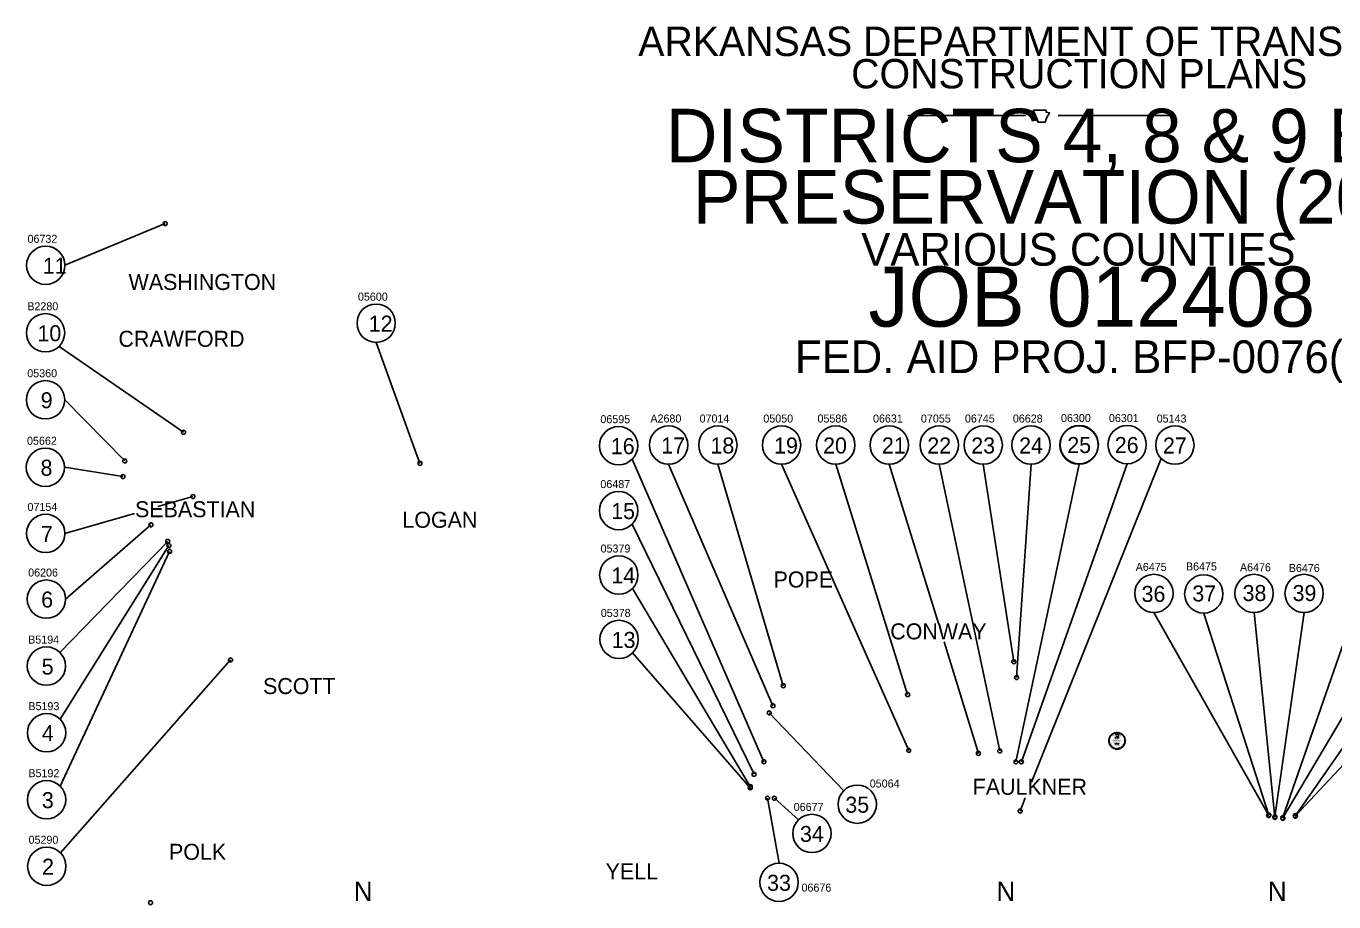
# Model space of a CAD drawing. Extents: x -13171 to 18763, y -8840 to 11152.
# Drawn here: x -13171 to 6418, y -1964 to 11152 of the extents above; entities that cross this region are included whole.
import ezdxf

# ---------------------------------------------------------------- set-up
doc = ezdxf.new("R2010")
doc.units = 0
for name, color, linetype in [('Level 1', 7, 'Continuous'), ('Level 2', 7, 'Continuous'), ('Level 46', 7, 'Continuous'), ('Level 48', 7, 'Continuous'), ('Level 50', 7, 'Continuous')]:
    doc.layers.add(name, color=color, linetype=linetype)

msp = doc.modelspace()

# ---------------------------------------------------------------- linework, layer by layer
at = {"layer": 'Level 1'}
for p, q in [((39, 9812), (1800, 9812)), ((2289, 9812), (4051, 9812))]:
    msp.add_line(p, q, dxfattribs=at)
msp.add_lwpolyline([(1915, 9901), (1952, 9803), (1952, 9743), (1982, 9736), (1982, 9714), (2094, 9714), (2116, 9773), (2161, 9856), (2108, 9862), (2108, 9893), (1923, 9893)], dxfattribs=at)
at = {"layer": 'Level 46'}
for p, q in [((3047, 438), (3046, 443)), ((3047, 458), (3047, 464)), ((3047, 448), (3047, 453)), ((3048, 428), (3047, 433)), ((3048, 468), (3049, 474)), ((3050, 418), (3049, 423)), ((3051, 478), (3052, 484)), ((3053, 408), (3051, 413)), ((3052, 450), (3053, 456)), ((3052, 441), (3052, 446)), ((3053, 460), (3054, 466)), ((3053, 431), (3053, 436)), ((3054, 488), (3055, 493)), ((3054, 470), (3056, 475)), ((3055, 421), (3054, 427)), ((3057, 398), (3055, 403)), ((3058, 412), (3056, 417)), ((3057, 498), (3059, 503)), ((3057, 479), (3058, 485)), ((3061, 403), (3059, 408)), ((3061, 389), (3059, 394)), ((3060, 489), (3062, 494)), ((3062, 507), (3064, 512)), ((3065, 394), (3063, 399)), ((3064, 498), (3066, 503)), ((3067, 516), (3070, 520)), ((3068, 506), (3071, 511)), ((3073, 524), (3076, 528)), ((3073, 515), (3077, 519)), ((3079, 523), (3083, 527)), ((3080, 532), (3083, 536)), ((3086, 530), (3090, 534)), ((3087, 539), (3091, 543)), ((3093, 537), (3097, 540)), ((3095, 546), (3099, 549)), ((3100, 543), (3105, 546)), ((3103, 552), (3108, 555)), ((3108, 548), (3113, 551)), ((3112, 557), (3117, 559)), ((3117, 553), (3122, 555)), ((3121, 561), (3126, 564)), ((3126, 557), (3131, 559)), ((3131, 565), (3136, 567)), ((3135, 560), (3140, 562)), ((3141, 568), (3146, 569)), ((3153, 499), (3142, 499)), ((3142, 499), (3151, 492)), ((3153, 404), (3142, 404)), ((3142, 404), (3151, 398)), ((3148, 503), (3144, 492)), ((3144, 492), (3153, 499)), ((3148, 408), (3144, 398)), ((3144, 398), (3153, 404)), ((3145, 563), (3150, 564)), ((3147, 497), (3148, 497)), ((3147, 402), (3148, 402)), ((3151, 492), (3148, 503)), ((3148, 498), (3148, 496)), ((3151, 398), (3148, 408)), ((3148, 403), (3148, 402)), ((3151, 570), (3156, 571)), ((3154, 565), (3160, 565)), ((3161, 571), (3167, 572)), ((3164, 566), (3169, 566)), ((3176, 499), (3165, 499)), ((3165, 499), (3174, 492)), ((3176, 404), (3165, 404)), ((3165, 404), (3174, 398)), ((3171, 503), (3167, 492)), ((3167, 492), (3176, 499)), ((3171, 408), (3167, 398)), ((3167, 398), (3176, 404)), ((3170, 497), (3172, 497)), ((3170, 402), (3172, 402)), ((3171, 571), (3177, 571)), ((3174, 492), (3171, 503)), ((3171, 498), (3171, 496)), ((3174, 398), (3171, 408)), ((3171, 403), (3171, 402)), ((3174, 566), (3179, 565)), ((3182, 571), (3187, 571)), ((3184, 565), (3189, 564)), ((3199, 499), (3188, 499)), ((3188, 499), (3197, 492)), ((3199, 404), (3188, 404)), ((3188, 404), (3197, 398)), ((3194, 503), (3190, 492)), ((3190, 492), (3199, 499)), ((3194, 408), (3190, 398)), ((3190, 398), (3199, 404)), ((3192, 570), (3197, 569)), ((3193, 564), (3198, 562)), ((3193, 497), (3195, 497)), ((3193, 402), (3195, 402)), ((3197, 492), (3194, 503)), ((3194, 498), (3194, 496)), ((3197, 398), (3194, 408)), ((3194, 403), (3194, 402)), ((3202, 568), (3207, 566)), ((3203, 561), (3208, 560)), ((3212, 565), (3217, 563)), ((3212, 558), (3217, 556)), ((3221, 561), (3226, 559)), ((3221, 555), (3226, 552)), ((3230, 556), (3235, 554)), ((3230, 550), (3234, 547)), ((3238, 545), (3242, 542)), ((3239, 551), (3244, 548)), ((3246, 539), (3250, 535)), ((3247, 545), (3252, 542)), ((3253, 532), (3257, 528)), ((3255, 538), (3259, 535)), ((3260, 525), (3263, 521)), ((3262, 531), (3266, 527)), ((3266, 518), (3269, 513)), ((3269, 523), (3272, 519)), ((3271, 510), (3274, 505)), ((3275, 515), (3278, 510)), ((3278, 397), (3275, 392)), ((3276, 501), (3278, 496)), ((3280, 506), (3283, 501)), ((3280, 492), (3282, 487)), ((3282, 406), (3280, 401)), ((3284, 397), (3282, 392)), ((3285, 415), (3283, 410)), ((3284, 483), (3285, 478)), ((3285, 497), (3287, 492)), ((3286, 474), (3287, 468)), ((3287, 425), (3286, 420)), ((3288, 407), (3286, 401)), ((3288, 487), (3290, 482)), ((3288, 464), (3288, 458)), ((3288, 435), (3288, 429)), ((3289, 454), (3289, 449)), ((3289, 444), (3289, 439)), ((3291, 416), (3290, 411)), ((3291, 477), (3293, 472)), ((3293, 426), (3292, 421)), ((3293, 467), (3294, 462)), ((3294, 457), (3295, 452)), ((3294, 437), (3294, 431)), ((3295, 447), (3295, 441)), ((3066, 380), (3063, 385)), ((3070, 385), (3067, 390)), ((3072, 372), (3069, 376)), ((3075, 377), (3072, 382)), ((3079, 364), (3075, 368)), ((3082, 369), (3078, 374)), ((3086, 357), (3082, 360)), ((3088, 362), (3085, 366)), ((3094, 350), (3090, 353)), ((3096, 356), (3092, 360)), ((3102, 344), (3098, 347)), ((3103, 350), (3099, 353)), ((3111, 339), (3106, 341)), ((3112, 345), (3107, 348)), ((3120, 334), (3115, 336)), ((3120, 340), (3116, 343)), ((3129, 336), (3124, 339)), ((3130, 330), (3125, 332)), ((3139, 333), (3134, 335)), ((3140, 327), (3134, 329)), ((3148, 331), (3143, 332)), ((3150, 325), (3144, 326)), ((3158, 330), (3152, 331)), ((3160, 324), (3154, 324)), ((3168, 329), (3162, 329)), ((3170, 323), (3165, 323)), ((3177, 329), (3172, 329)), ((3180, 324), (3175, 323)), ((3187, 330), (3182, 330)), ((3190, 325), (3185, 324)), ((3197, 332), (3191, 331)), ((3201, 327), (3195, 326)), ((3206, 334), (3201, 333)), ((3210, 330), (3205, 328)), ((3215, 338), (3210, 336)), ((3220, 334), (3215, 331)), ((3224, 342), (3219, 340)), ((3229, 338), (3224, 335)), ((3233, 347), (3228, 344)), ((3238, 343), (3234, 340)), ((3241, 352), (3236, 349)), ((3246, 349), (3242, 346)), ((3249, 358), (3244, 355)), ((3254, 356), (3250, 352)), ((3256, 365), (3252, 361)), ((3262, 363), (3258, 359)), ((3262, 372), (3259, 368)), ((3268, 380), (3265, 376)), ((3268, 371), (3265, 366)), ((3273, 388), (3270, 384)), ((3274, 379), (3271, 374)), ((3280, 388), (3277, 383))]:
    msp.add_line(p, q, dxfattribs=at)
for points in [[(3053, 436), (3046, 443)], [(3053, 456), (3047, 464)], [(3053, 454), (3047, 462)], [(3052, 452), (3047, 460)], [(3052, 450), (3047, 458)], [(3052, 446), (3047, 453)], [(3052, 444), (3047, 452)], [(3052, 442), (3047, 450)], [(3052, 441), (3047, 448)], [(3053, 435), (3047, 441)], [(3053, 433), (3047, 440)], [(3053, 431), (3047, 438)], [(3054, 427), (3047, 433)], [(3053, 460), (3048, 468)], [(3055, 425), (3048, 431)], [(3055, 423), (3048, 429)], [(3055, 421), (3048, 428)], [(3054, 466), (3049, 474)], [(3054, 464), (3049, 472)], [(3053, 462), (3049, 470)], [(3056, 417), (3049, 423)], [(3057, 415), (3049, 421)], [(3057, 414), (3050, 419)], [(3058, 412), (3050, 418)], [(3055, 473), (3051, 482)], [(3055, 472), (3051, 480)], [(3054, 470), (3051, 478)], [(3059, 408), (3051, 413)], [(3056, 475), (3052, 484)], [(3060, 406), (3052, 411)], [(3061, 404), (3053, 409)], [(3061, 403), (3053, 408)], [(3057, 481), (3054, 490)], [(3057, 479), (3054, 488)], [(3058, 485), (3055, 493)], [(3058, 483), (3055, 492)], [(3063, 399), (3055, 403)], [(3064, 397), (3055, 401)], [(3064, 395), (3056, 400)], [(3060, 489), (3057, 498)], [(3065, 394), (3057, 398)], [(3060, 490), (3058, 499)], [(3062, 494), (3059, 503)], [(3061, 492), (3059, 501)], [(3067, 390), (3059, 394)], [(3068, 388), (3059, 392)], [(3064, 498), (3062, 507)], [(3064, 499), (3063, 509)], [(3066, 503), (3064, 512)], [(3065, 501), (3064, 510)], [(3068, 506), (3067, 516)], [(3069, 508), (3068, 517)], [(3070, 510), (3069, 519)], [(3071, 511), (3070, 520)], [(3073, 515), (3073, 524)], [(3074, 516), (3074, 526)], [(3075, 518), (3075, 527)], [(3077, 519), (3076, 528)], [(3079, 523), (3080, 532)], [(3080, 524), (3081, 533)], [(3082, 525), (3082, 535)], [(3083, 527), (3083, 536)], [(3086, 530), (3087, 539)], [(3087, 531), (3088, 540)], [(3088, 532), (3090, 542)], [(3090, 534), (3091, 543)], [(3093, 537), (3095, 546)], [(3094, 538), (3096, 547)], [(3096, 539), (3098, 548)], [(3097, 540), (3099, 549)], [(3100, 543), (3103, 552)], [(3102, 544), (3105, 553)], [(3103, 545), (3106, 554)], [(3105, 546), (3108, 555)], [(3108, 548), (3112, 557)], [(3110, 549), (3114, 558)], [(3112, 550), (3115, 559)], [(3113, 551), (3117, 559)], [(3117, 553), (3121, 561)], [(3119, 554), (3123, 562)], [(3120, 554), (3125, 563)], [(3122, 555), (3126, 564)], [(3126, 557), (3131, 565)], [(3128, 558), (3133, 566)], [(3129, 558), (3134, 566)], [(3131, 559), (3136, 567)], [(3135, 560), (3141, 568)], [(3137, 561), (3143, 568)], [(3139, 561), (3144, 569)], [(3140, 562), (3146, 569)], [(3145, 563), (3151, 570)], [(3146, 563), (3153, 570)], [(3148, 564), (3154, 571)], [(3151, 535), (3148, 541), (3198, 541), (3194, 536), (3198, 536), (3200, 536), (3203, 536)], [(3152, 535), (3149, 541), (3197, 541), (3193, 535), (3198, 535), (3200, 535), (3203, 535)], [(3150, 564), (3156, 571)], [(3154, 565), (3161, 571)], [(3190, 514), (3190, 513), (3189, 512), (3189, 510), (3189, 506), (3161, 506), (3161, 511), (3161, 512), (3160, 512), (3156, 512), (3155, 513)], [(3156, 565), (3163, 571)], [(3190, 515), (3189, 514), (3189, 512), (3188, 510), (3188, 507), (3162, 507), (3162, 511), (3162, 512), (3160, 513), (3156, 513), (3156, 514)], [(3158, 565), (3165, 571)], [(3160, 565), (3167, 572)], [(3164, 566), (3171, 571)], [(3166, 566), (3173, 571)], [(3168, 566), (3175, 571)], [(3169, 566), (3177, 571)], [(3174, 566), (3182, 571)], [(3175, 566), (3183, 571)], [(3177, 566), (3185, 571)], [(3179, 565), (3187, 571)], [(3184, 565), (3192, 570)], [(3185, 565), (3193, 569)], [(3187, 565), (3195, 569)], [(3189, 564), (3197, 569)], [(3193, 564), (3202, 568)], [(3195, 563), (3203, 567)], [(3197, 563), (3205, 567)], [(3198, 562), (3207, 566)], [(3203, 561), (3212, 565)], [(3204, 561), (3213, 564)], [(3206, 560), (3215, 563)], [(3208, 560), (3217, 563)], [(3212, 558), (3221, 561)], [(3214, 558), (3223, 560)], [(3215, 557), (3224, 559)], [(3217, 556), (3226, 559)], [(3221, 555), (3230, 556)], [(3223, 554), (3232, 555)], [(3224, 553), (3234, 555)], [(3226, 552), (3235, 554)], [(3230, 550), (3239, 551)], [(3231, 549), (3241, 550)], [(3233, 548), (3242, 549)], [(3234, 547), (3244, 548)], [(3238, 545), (3247, 545)], [(3239, 544), (3249, 544)], [(3241, 543), (3250, 543)], [(3242, 542), (3252, 542)], [(3246, 539), (3255, 538)], [(3247, 538), (3256, 537)], [(3249, 537), (3258, 536)], [(3250, 535), (3259, 535)], [(3253, 532), (3262, 531)], [(3254, 531), (3264, 530)], [(3256, 530), (3265, 528)], [(3257, 528), (3266, 527)], [(3260, 525), (3269, 523)], [(3261, 524), (3270, 522)], [(3262, 523), (3271, 520)], [(3263, 521), (3272, 519)], [(3266, 518), (3275, 515)], [(3267, 516), (3276, 513)], [(3268, 515), (3277, 512)], [(3269, 513), (3278, 510)], [(3271, 510), (3280, 506)], [(3272, 508), (3281, 504)], [(3273, 506), (3282, 503)], [(3274, 505), (3283, 501)], [(3275, 392), (3277, 383)], [(3276, 501), (3285, 497)], [(3276, 394), (3278, 385)], [(3277, 499), (3285, 495)], [(3277, 396), (3279, 386)], [(3278, 498), (3286, 493)], [(3278, 397), (3280, 388)], [(3278, 496), (3287, 492)], [(3280, 492), (3288, 487)], [(3280, 403), (3283, 394)], [(3280, 401), (3282, 392)], [(3281, 491), (3289, 485)], [(3281, 404), (3283, 395)], [(3282, 489), (3289, 484)], [(3282, 487), (3290, 482)], [(3282, 406), (3284, 397)], [(3283, 410), (3286, 401)], [(3284, 483), (3291, 477)], [(3284, 481), (3292, 476)], [(3284, 414), (3287, 405)], [(3284, 412), (3287, 403)], [(3285, 479), (3292, 474)], [(3285, 478), (3293, 472)], [(3285, 415), (3288, 407)], [(3286, 474), (3293, 467)], [(3286, 472), (3293, 465)], [(3286, 421), (3290, 413)], [(3286, 420), (3290, 411)], [(3287, 470), (3294, 464)], [(3287, 468), (3294, 462)], [(3287, 425), (3291, 416)], [(3287, 423), (3290, 415)], [(3288, 464), (3294, 457)], [(3288, 462), (3295, 455)], [(3288, 460), (3295, 453)], [(3288, 458), (3295, 452)], [(3288, 435), (3293, 426)], [(3288, 433), (3293, 425)], [(3288, 431), (3292, 423)], [(3288, 429), (3292, 421)], [(3289, 454), (3295, 447)], [(3289, 452), (3295, 445)], [(3289, 451), (3295, 443)], [(3289, 449), (3295, 441)], [(3289, 444), (3294, 437)], [(3289, 443), (3294, 435)], [(3289, 441), (3294, 433)], [(3289, 439), (3294, 431)], [(3069, 387), (3060, 390)], [(3070, 385), (3061, 389)], [(3072, 382), (3063, 385)], [(3073, 380), (3064, 383)], [(3074, 379), (3066, 382)], [(3075, 377), (3066, 380)], [(3078, 374), (3069, 376)], [(3079, 372), (3070, 375)], [(3080, 371), (3071, 373)], [(3082, 369), (3072, 372)], [(3085, 366), (3075, 368)], [(3086, 365), (3076, 366)], [(3087, 364), (3078, 365)], [(3088, 362), (3079, 364)], [(3092, 360), (3082, 360)], [(3093, 358), (3083, 359)], [(3094, 357), (3085, 358)], [(3096, 356), (3086, 357)], [(3099, 353), (3090, 353)], [(3100, 352), (3091, 352)], [(3102, 351), (3093, 351)], [(3103, 350), (3094, 350)], [(3107, 348), (3098, 347)], [(3109, 347), (3099, 346)], [(3110, 346), (3101, 345)], [(3112, 345), (3102, 344)], [(3116, 343), (3106, 341)], [(3117, 342), (3108, 340)], [(3119, 341), (3110, 339)], [(3120, 340), (3111, 339)], [(3124, 339), (3115, 336)], [(3126, 338), (3117, 335)], [(3128, 337), (3119, 335)], [(3129, 336), (3120, 334)], [(3134, 335), (3125, 332)], [(3135, 335), (3126, 331)], [(3137, 334), (3128, 331)], [(3139, 333), (3130, 330)], [(3143, 332), (3134, 329)], [(3145, 332), (3136, 328)], [(3147, 332), (3138, 328)], [(3148, 331), (3140, 327)], [(3152, 331), (3144, 326)], [(3154, 330), (3146, 326)], [(3156, 330), (3148, 325)], [(3158, 330), (3150, 325)], [(3162, 329), (3154, 324)], [(3164, 329), (3156, 324)], [(3166, 329), (3158, 324)], [(3168, 329), (3160, 324)], [(3172, 329), (3165, 323)], [(3174, 329), (3166, 323)], [(3176, 329), (3168, 323)], [(3177, 329), (3170, 323)], [(3182, 330), (3175, 323)], [(3184, 330), (3177, 323)], [(3185, 330), (3179, 324)], [(3187, 330), (3180, 324)], [(3191, 331), (3185, 324)], [(3193, 331), (3187, 324)], [(3195, 332), (3189, 325)], [(3197, 332), (3190, 325)], [(3201, 333), (3195, 326)], [(3203, 334), (3197, 326)], [(3205, 334), (3199, 327)], [(3206, 334), (3201, 327)], [(3210, 336), (3205, 328)], [(3212, 337), (3207, 329)], [(3214, 337), (3209, 329)], [(3215, 338), (3210, 330)], [(3219, 340), (3215, 331)], [(3221, 340), (3217, 332)], [(3223, 341), (3218, 333)], [(3224, 342), (3220, 334)], [(3228, 344), (3224, 335)], [(3230, 345), (3226, 336)], [(3231, 346), (3228, 337)], [(3233, 347), (3229, 338)], [(3236, 349), (3234, 340)], [(3238, 350), (3235, 341)], [(3240, 351), (3237, 342)], [(3241, 352), (3238, 343)], [(3244, 355), (3242, 346)], [(3246, 356), (3244, 347)], [(3247, 357), (3245, 348)], [(3249, 358), (3246, 349)], [(3252, 361), (3250, 352)], [(3253, 362), (3252, 353)], [(3254, 364), (3253, 355)], [(3256, 365), (3254, 356)], [(3259, 368), (3258, 359)], [(3260, 370), (3259, 360)], [(3261, 371), (3260, 362)], [(3262, 372), (3262, 363)], [(3265, 376), (3265, 366)], [(3266, 377), (3266, 368)], [(3267, 379), (3267, 369)], [(3268, 380), (3268, 371)], [(3270, 384), (3271, 374)], [(3271, 385), (3272, 376)], [(3272, 387), (3273, 378)], [(3273, 388), (3274, 379)]]:
    msp.add_lwpolyline(points, dxfattribs=at)
at = {"layer": 'Level 48'}
for p, q in [((-12591, 7570), (-11089, 8194)), ((-12678, 6356), (-10814, 5069)), ((-7928, 6416), (-7272, 4603)), ((-12594, 5555), (-11694, 4639)), ((-12597, 4545), (-11721, 4406)), ((-4093, 4664), (-2120, 135)), ((-3547, 4591), (-1984, 972)), ((-2809, 4591), (-1829, 1273)), ((-1855, 4591), (51, 303)), ((-1043, 4591), (34, 1140)), ((-241, 4591), (494, 2207)), ((507, 4591), (1414, 296)), ((1166, 4591), (1624, 1632)), ((2601, 4591), (1655, 133)), ((1883, 4591), (1666, 1395)), ((3322, 4597), (1738, 133)), ((3834, 4675), (1891, -173)), ((-11198, 3955), (-10673, 4106)), ((-12591, 3554), (-11550, 3854)), ((-12581, 2570), (-11302, 3683)), ((-4093, 3693), (-2267, -53)), ((-12665, 1769), (-11050, 3435)), ((-12662, 772), (-11033, 3371)), ((-12662, -232), (-11022, 3284)), ((-4090, 2728), (-2324, -239)), ((3723, 2368), (5442, -671)), ((4471, 2354), (5445, -664)), ((5223, 2368), (5534, -700)), ((5973, 2368), (5536, -692)), ((6723, 2368), (5650, -713)), ((7477, 2375), (5656, -708)), ((8024, 2459), (5838, -681)), ((8777, 2465), (5842, -674)), ((580, 1928), (1094, 260)), ((-12659, -1229), (-10110, 1659)), ((-4086, 1763), (-2324, -256)), ((-925, -299), (-2040, 866)), ((-1893, -1385), (-2065, -411)), ((-1602, -737), (-1963, -412)), ((1796, -408), (1718, -604))]:
    msp.add_line(p, q, dxfattribs=at)
for centre, radius in [((-11089, 8194), 30.2), ((-12878, 7570), 287), ((-7928, 6703), 287), ((-12881, 6559), 287), ((-12881, 5555), 287), ((-10814, 5069), 30.2), ((-4296, 4867), 287), ((-3547, 4878), 287), ((-2809, 4878), 287), ((-1855, 4878), 287), ((-1043, 4878), 287), ((-241, 4878), 287), ((507, 4878), 287), ((1166, 4878), 287), ((1883, 4878), 287), ((1883, 4878), 287), ((2601, 4878), 287), ((2604, 4884), 287), ((2604, 4884), 287), ((3322, 4884), 287), ((4037, 4878), 287), ((-12884, 4545), 287), ((-11694, 4639), 30.2), ((-7272, 4603), 30.2), ((-11721, 4406), 30.2), ((-10673, 4106), 30.2), ((-4296, 3896), 287), ((-12878, 3554), 287), ((-11302, 3683), 30.2), ((-11050, 3435), 30.2), ((-11033, 3371), 30.2), ((-11022, 3284), 30.2), ((-4293, 2931), 287), ((3723, 2655), 287), ((5223, 2655), 287), ((5973, 2655), 287), ((-12868, 2570), 287), ((4470, 2648), 287), ((-4289, 1966), 287), ((-12868, 1567), 287), ((-10110, 1659), 30.2), ((1624, 1632), 30.2), ((1666, 1395), 30.2), ((-1829, 1273), 30.2), ((-1984, 972), 30.2), ((34, 1140), 30.2), ((-12865, 569), 287), ((-2040, 866), 30.2), ((51, 303), 30.2), ((1094, 260), 30.2), ((1414, 296), 30.2), ((-2120, 135), 30.2), ((1655, 133), 30.2), ((1738, 133), 30.2), ((-12865, -434), 287), ((-2267, -53), 30.2), ((-2324, -239), 30.2), ((-2324, -256), 30.2), ((-2065, -411), 30.2), ((-1963, -412), 30.2), ((-721, -502), 287), ((1719, -604), 30.2), ((-1400, -940), 287), ((5442, -671), 30.2), ((5445, -664), 30.2), ((5534, -700), 30.2), ((5536, -692), 30.2), ((5653, -706), 30.2), ((5654, -714), 30.2), ((5841, -673), 30.2), ((5842, -682), 30.2), ((-12862, -1432), 287), ((-1893, -1672), 287), ((-11308, -1977), 30.2)]:
    msp.add_circle(centre, radius, dxfattribs=at)

# ---------------------------------------------------------------- texts
at = {"layer": 'Level 1'}
msp.add_text('FED. AID PROJ. BFP-0076(268)', height=489.2, dxfattribs=at).set_placement((-1655, 5956))
at = {"layer": 'Level 2'}
for s, height, p in [('ARKANSAS DEPARTMENT OF TRANSPORTATION', 440, (-4002, 10705)), ('CONSTRUCTION PLANS', 440, (-812, 10220)), ('DISTRICTS 4, 8 & 9 BRIDGE', 800, (-3588, 9114)), ('PRESERVATION (2022) (S)', 800, (-3184, 8195)), ('VARIOUS COUNTIES', 489.2, (-662, 7564)), ('JOB 012408', 900, (-554, 6651)), ('WASHINGTON', 240, (-11637, 7200)), ('CRAWFORD', 240, (-11789, 6349)), ('SEBASTIAN', 240, (-11540, 3796)), ('LOGAN', 240, (-7535, 3638)), ('POPE', 240, (-1975, 2744)), ('CONWAY', 240, (-227, 1967)), ('SCOTT', 240, (-9623, 1148)), ('FAULKNER', 240, (1008, -361)), ('POLK', 240, (-11031, -1335)), ('YELL', 240, (-4491, -1627))]:
    msp.add_text(s, height=height, dxfattribs=at).set_placement(p)
at = {"layer": 'Level 46'}
for s, height, rotation, p in [('S', 15, 286.9475, (3062, 421)), ('C', 15, 294.2435, (3066, 408)), ('O', 15, 301.9044, (3072, 394)), ('S', 9.9, 19.7726, (3125, 538)), ('T', 9.9, 16.9015, (3138, 544)), ('A', 9.9, 8.6788, (3150, 547)), ('T', 9.9, 1.4789, (3162, 549)), ('E', 9.9, 356.672, (3175, 549)), ('O', 9.9, 341.2218, (3199, 545)), ('F', 9.9, 335.3628, (3212, 540)), ('R', 15, 55.7221, (3260, 378)), ('R', 15, 63.7477, (3269, 391)), ('Y', 15, 71.7733, (3276, 405)), ('T', 15, 309.93, (3080, 381)), ('T', 15, 317.226, (3090, 370)), ('P', 15, 332.1828, (3112, 351)), ('.', 15, 340.2084, (3126, 344)), ('T', 15, 351.882, (3148, 337)), ('H', 15, 359.178, (3162, 335)), ('O', 15, 7.9332, (3180, 335)), ('R', 15, 15.9589, (3195, 337)), ('N', 15, 23.9845, (3210, 342)), ('S', 15, 32.7397, (3226, 349)), ('B', 15, 40.0357, (3238, 357)), ('E', 15, 48.0613, (3250, 367))]:
    msp.add_text(s, height=height, rotation=rotation, dxfattribs=at).set_placement(p)
for s, height, p in [('PROFESSIONAL', 16.15, (3077, 443)), ('ARKANSAS', 16.2, (3107, 516)), ('ENGINEER', 16.2, (3106, 417)), ('LICENSED', 16.2, (3110, 469)), ('No.10887', 15.6, (3121, 376))]:
    msp.add_text(s, height=height, dxfattribs=at).set_placement(p)
at = {"layer": 'Level 48'}
for s, height, p in [('11', 240, (-12921, 7443)), ('10', 240, (-13002, 6432)), ('12', 240, (-8039, 6576)), ('9', 240, (-12953, 5429)), ('16', 240, (-4413, 4741)), ('17', 240, (-3658, 4751)), ('18', 240, (-2920, 4751)), ('19', 240, (-1967, 4751)), ('20', 240, (-1233, 4751)), ('21', 240, (-352, 4751)), ('22', 240, (328, 4751)), ('23', 240, (987, 4751)), ('24', 240, (1704, 4751)), ('25', 240, (2425, 4758)), ('26', 240, (3137, 4758)), ('27', 240, (3858, 4751)), ('8', 240, (-12956, 4418)), ('15', 240, (-4407, 3769)), ('7', 240, (-12949, 3427)), ('14', 240, (-4404, 2804)), ('36', 240, (3538, 2528)), ('37', 240, (4298, 2535)), ('38', 240, (5051, 2541)), ('39', 240, (5800, 2541)), ('6', 240, (-12946, 2444)), ('13', 240, (-4400, 1839)), ('5', 240, (-12939, 1440)), ('4', 240, (-12936, 443)), ('3', 240, (-12936, -561)), ('35', 240, (-900, -629)), ('34', 240, (-1579, -1067)), ('2', 240, (-12933, -1558)), ('33', 240, (-2072, -1799)), ('N', 293, (-8264, -1954)), ('N', 293, (1363, -1954)), ('N', 293, (5429, -1954))]:
    msp.add_text(s, height=height, dxfattribs=at).set_placement(p)
at = {"layer": 'Level 50'}
for s, p in [('06732', (-13151, 7907)), ('05600', (-8201, 7040)), ('B2280', (-13154, 6896)), ('05360', (-13154, 5893)), ('06595', (-4569, 5205)), ('A2680', (-3820, 5215)), ('07014', (-3083, 5215)), ('05050', (-2128, 5215)), ('05586', (-1317, 5215)), ('06631', (-485, 5215)), ('07055', (233, 5215)), ('06745', (892, 5215)), ('06628', (1610, 5215)), ('06300', (2331, 5222)), ('06301', (3049, 5222)), ('05143', (3764, 5215)), ('05662', (-13158, 4882)), ('06487', (-4569, 4233)), ('07154', (-13151, 3891)), ('05379', (-4566, 3268)), ('06206', (-13141, 2908)), ('A6475', (3450, 2992)), ('B6475', (4203, 2999)), ('A6476', (5012, 2987)), ('B6476', (5743, 2976)), ('05378', (-4563, 2303)), ('B5194', (-13141, 1904)), ('B5193', (-13138, 907)), ('B5192', (-13138, -97)), ('05064', (-534, -252)), ('06677', (-1673, -603)), ('05290', (-13135, -1094)), ('06676', (-1556, -1811))]:
    msp.add_text(s, height=120, dxfattribs=at).set_placement(p)

doc.saveas('drawing.dxf')
